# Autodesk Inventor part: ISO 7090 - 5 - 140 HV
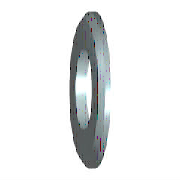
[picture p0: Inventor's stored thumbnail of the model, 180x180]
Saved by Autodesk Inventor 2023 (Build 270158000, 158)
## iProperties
Created: 2015-02
Part Number: ISO 7090 - 5 - 140 HV
Material: Stainless Steel
Description: Plain washers, charmfered - Normal series - Product grade A
Document SubType Name: Modeling
Standard: ISO 7090
Designer: Cadskolen
Standard Revision: Second edition 2000-06-01
Standards Organization: ISO
Language: en-US
Size Designation: 5 - 140 HV
Categories: <MemberInstance><Categories><Category DisplayName="Fasteners" InternalName="e4da775c-781d-43d5-af7c-5136215cf5a6" Mnemonic="FSTN"><Category DisplayName="Washers
Density: 8 g/cm^3
Appearance: Semi-Polished
IsCustomPart: 0
Author: Cadskolen
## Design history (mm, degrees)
sketch "Sketch"
  geometry: C1 r 5 at (0, 0); C2 r 2.65 at (0, 0); 1 further point
  constraints: 2 centre point, 2 coincident
  dimensions: "d0" = 5.3 diameter of C2 (= SD1); "d1" = 10 diameter of C1 (= SD2)
extrude "Body" new body sketch "Sketch" distance "d2" = 1 (= SD); taper "d3" = 0 deg
workaxis "Work Axis1"
workplane "Work Plane1"
body "Solid1"
chamfer "Chamfer" distance "d4" = 0.5 (= PHH); stored, may be unused: angle "d5" = 45 deg, second distance "d8" = 0.5 (= PHH)
other parameters: "SD1" = 5.3 [user parameter; used in 1 equation term], "SD2" = 10 [user parameter; used in 1 equation term], "SD" = 1 [user parameter; used in 1 equation term], "PHH" = 0.5 [user parameter; used in 2 equation terms], "FAWI" = 45 deg [user parameter], "d6" = 0, "d7" = 0, "d9" = 0, "d10" = 0, "NND" = 5 [user parameter]
